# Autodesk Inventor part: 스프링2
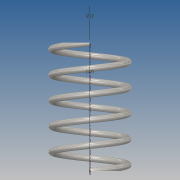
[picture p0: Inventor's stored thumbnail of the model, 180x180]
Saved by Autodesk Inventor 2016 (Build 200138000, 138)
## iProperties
Created: 2016-01
Part Number: 스프링2
Material: 스테인레스 스틸
Document SubType Name: Modeling
Designer: Administrator
Density: 8 g/cm^3
Appearance: 반연마
Mass: 8.57814 g
Surface Area: 21.709 cm^2
Volume: 1.07227 cm^3
Author: Administrator
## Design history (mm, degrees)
sketch "스케치1"
  geometry: L1 (0, 0)-(11, 0); L2 (11, 0)-(11, 36.411); L3 (11, 36.411)-(0, 36.411); L4 (0, 36.411)-(0, 0); C1 r 1 at (11, 0)
  constraints: 8 end point, 2 parallel, 1 centre point, 1 coincident, 1 horizontal, 1 perpendicular
  dimensions: "d0" = 2 diameter of C1; "d1" = 36.4112 distance of L1.end L2.end (derived); "d2" = 22 diameter of L2 L4
feature "코일1" pitch "d3" = 10; turns "d5" = 5; dims "d4" = 36.4112 (= d1), "d6" = 0, angle "d7" = 90 deg, angle "d8" = 90 deg, "d9" = 0, "d10" = 0
sketch "스케치2"
  geometry: L1 (5.3, 0)-(-21.597, 0); L2 (-21.597, 0)-(-21.597, -10.619); L3 (-21.597, -10.619)-(5.3, -10.619); L4 (5.3, -10.619)-(5.3, 0); 3 further points
  constraints: 8 end point, 2 parallel, 1 horizontal, 1 horizontal alignment, 1 perpendicular, 1 point on line
extrude "돌출1" cut sketch "스케치2" stored distance "d11" = 0; taper "d12" = 0 deg
sketch "스케치3"
  geometry: L1 (-4.261, 0)-(22.454, 0); L2 (22.454, 0)-(22.454, 6.999); L3 (22.454, 6.999)-(-4.261, 6.999); L4 (-4.261, 6.999)-(-4.261, 0); 3 further points
  constraints: 8 end point, 2 parallel, 1 horizontal, 1 horizontal alignment, 1 perpendicular, 1 point on line
extrude "돌출2" cut sketch "스케치3" stored distance "d13" = 0; taper "d14" = 0 deg
node "솔리드1"
